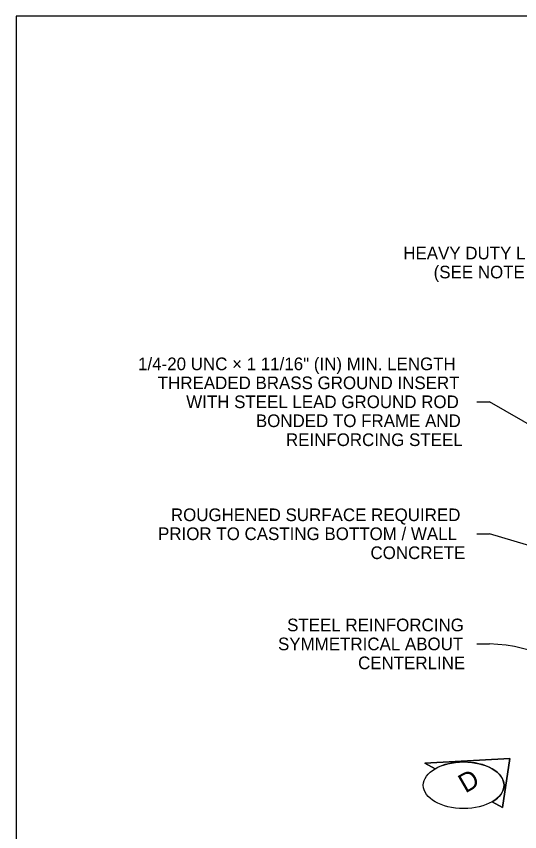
# Model space of a CAD drawing. Extents: x 99862 to 103151, y 100000 to 105076.
# Drawn here: x 99862 to 100499, y 104044 to 105076 of the extents above; entities that cross this region are included whole.
import ezdxf

# ---------------------------------------------------------------- set-up
doc = ezdxf.new("R2010")
doc.units = 0
for name, color, linetype in [('Level 1', 7, 'Continuous'), ('Level 15', 7, 'Continuous'), ('Level 20', 7, 'Continuous'), ('Level 9', 7, 'Continuous')]:
    doc.layers.add(name, color=color, linetype=linetype)

msp = doc.modelspace()

# ---------------------------------------------------------------- linework, layer by layer
at = {"layer": 'Level 1'}
msp.add_lwpolyline([(99862, 102999.5), (103151, 102999.5), (103151, 105075.5), (99862, 105075.5)], close=True, dxfattribs=at)
at = {"layer": 'Level 15'}
for p, q in [((100444.4, 104587.7), (100460.4, 104587.7)), ((100594.1, 104510.5), (100460.4, 104587.7)), ((100444.4, 104420.7), (100460.4, 104420.7)), ((100702.1, 104347.7), (100460.4, 104420.7)), ((100444.4, 104281.3), (100460.4, 104281.3))]:
    msp.add_line(p, q, dxfattribs=at)
msp.add_arc((100452.4, 104066.6), 214.9, 43.1541, 87.8525, dxfattribs=at)
at = {"layer": 'Level 9'}
for p, q in [((100486.1, 104136.1), (100378.8, 104130.6)), ((100378.8, 104130.6), (100486.1, 104136.1)), ((100476.7, 104074.1), (100486.1, 104136.1)), ((100486.1, 104136.1), (100476.7, 104074.1)), ((100378.8, 104130.6), (100391.6, 104123.3)), ((100391.6, 104123.3), (100378.8, 104130.6)), ((100463.9, 104081.5), (100476.7, 104074.1)), ((100476.7, 104074.1), (100463.9, 104081.5))]:
    msp.add_line(p, q, dxfattribs=at)
msp.add_ellipse((100427.7, 104102.4), major_axis=(-51.1, 0), ratio=0.57735, dxfattribs=at)
msp.add_ellipse((100427.7, 104102.4), major_axis=(-51.1, 0), ratio=0.57735, start_param=2.356307, end_param=5.497872, dxfattribs=at)

# ---------------------------------------------------------------- texts
at = {"layer": 'Level 20'}
for s, p in [('HEAVY DUTY LID', (100351.4, 104767.9)), ('(SEE NOTE 1)', (100389.8, 104743.9)), ('1/4-20 UNC × 1 11/16" (IN) MIN. LENGTH', (100016, 104627.7)), ('THREADED BRASS GROUND INSERT', (100040.9, 104603.7)), ('WITH STEEL LEAD GROUND ROD', (100076.9, 104579.7)), ('BONDED TO FRAME AND', (100165, 104555.7)), ('REINFORCING STEEL', (100203, 104531.7)), ('ROUGHENED SURFACE REQUIRED', (100057.5, 104436.7)), ('PRIOR TO CASTING BOTTOM / WALL', (100041.3, 104412.7)), ('CONCRETE', (100309.9, 104388.7)), ('STEEL REINFORCING', (100204.5, 104297.3)), ('SYMMETRICAL ABOUT', (100193, 104273.3)), ('CENTERLINE', (100294.2, 104249.3))]:
    msp.add_text(s, height=16, dxfattribs=at).set_placement(p)
msp.add_text('D', height=24, rotation=29.9987, dxfattribs=at).set_placement((100430, 104091.9))

doc.saveas('drawing.dxf')
